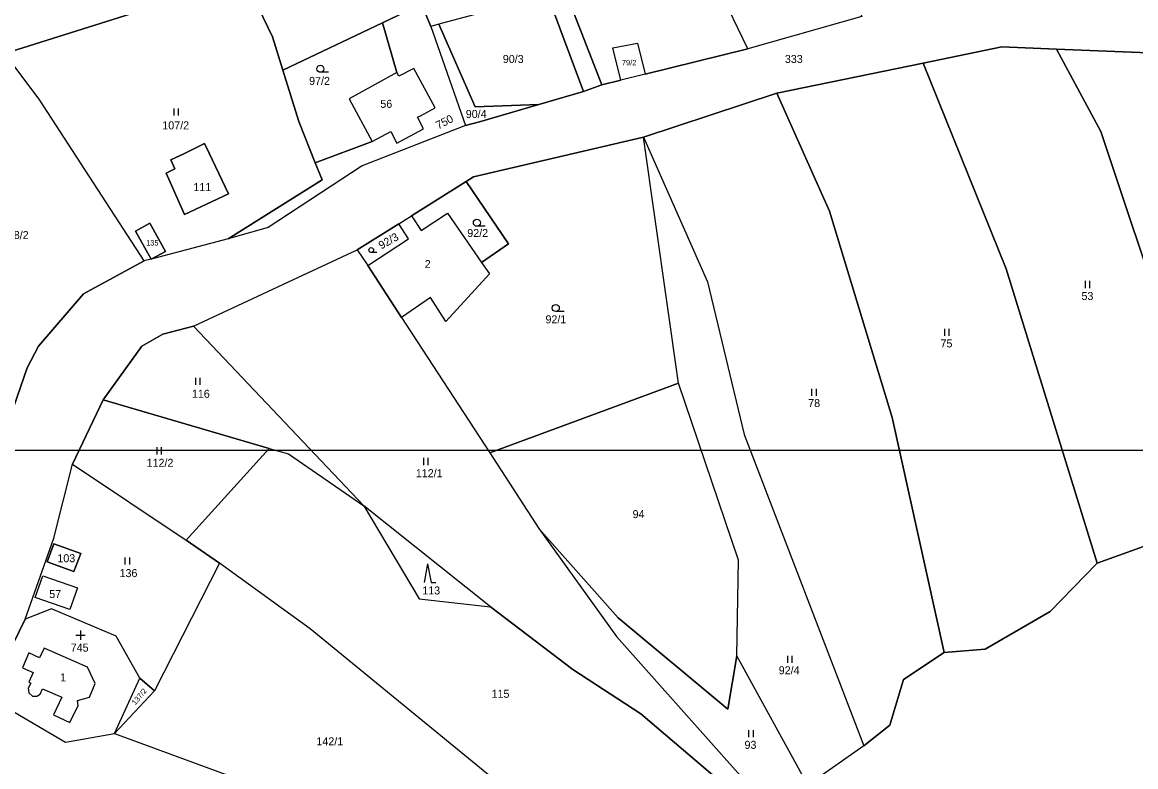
# Model space of a CAD drawing. Extents: x -590606 to -587796, y -1065936 to -1062515.
# Drawn here: x -588986.8 to -588750.2, y -1064072.1 to -1063914 of the extents above; entities that cross this region are included whole.
import ezdxf

# ---------------------------------------------------------------- set-up
doc = ezdxf.new("R2010")
doc.units = 0
for name, color, linetype in [('Default', 7, 'Continuous'), ('Parcela nároku', 7, 'Continuous'), ('Vrstva 30', 7, 'Continuous')]:
    doc.layers.add(name, color=color, linetype=linetype)

msp = doc.modelspace()

# ---------------------------------------------------------------- linework, layer by layer
at = {"layer": 'Default'}
msp.add_lwpolyline([(-590606.42, -1064004.87), (-587796.29, -1064004.87), (-587796.29, -1065935.82), (-590606.42, -1065935.82)], close=True, dxfattribs=at)
at = {"layer": 'Parcela nároku'}
for points in [[(-588933.91, -1063838.81), (-588924.82, -1063834.02), (-588903.58, -1063826.39), (-588900.04, -1063836.93), (-588899.24, -1063839.3), (-588896.62, -1063847.13), (-588895.87, -1063849.37), (-588892.19, -1063861.45), (-588875.17, -1063908.15), (-588898.29, -1063914.41), (-588900.01, -1063914.87), (-588901.55, -1063911.13), (-588901.96, -1063910.16), (-588903.1, -1063907.49), (-588906.06, -1063900.55), (-588920, -1063868.06), (-588927.08, -1063852.06)], [(-588927.08, -1063852.06), (-588920, -1063868.06), (-588906.06, -1063900.55), (-588903.1, -1063907.49), (-588901.96, -1063910.16), (-588910.23, -1063914.1), (-588931.41, -1063924.18), (-588933.62, -1063917.1), (-588939.65, -1063904.58), (-588952.08, -1063879.66), (-588958.1, -1063870.25)], [(-588888.44, -1063860.6), (-588892.19, -1063861.45), (-588875.17, -1063908.15), (-588867.52, -1063928.72), (-588863.64, -1063927.3), (-588875.2, -1063897.61)], [(-589010.57, -1063894.09), (-588981.38, -1063887.88), (-588977.05, -1063880.26), (-588973.04, -1063895.63), (-588966.91, -1063891.55), (-588956.54, -1063883.07), (-588952.08, -1063879.66), (-588939.65, -1063904.58), (-588990.51, -1063920.59)], [(-588999.26, -1063953.09), (-589016.29, -1063972.28), (-588989.28, -1063997.65), (-588985.76, -1063987.39), (-588983.36, -1063982.76), (-588973.8, -1063971.68), (-588960.88, -1063964.65), (-588983.18, -1063930.34), (-588990.51, -1063920.59), (-589010.57, -1063894.09), (-589025.93, -1063892.96), (-589037.53, -1063890.69)], [(-588857.5, -1063900.46), (-588875.2, -1063897.61), (-588863.64, -1063927.3), (-588859.62, -1063926.3), (-588861.33, -1063919.41), (-588856.05, -1063918.43), (-588854.45, -1063925.02), (-588832.67, -1063919.62), (-588836.75, -1063911.14), (-588842.82, -1063898.51)], [(-588836.75, -1063911.14), (-588812.67, -1063901.49), (-588808.45, -1063912.75), (-588832.67, -1063919.62)], [(-588959.37, -1063964.26), (-588960.88, -1063964.65), (-588983.18, -1063930.34), (-588990.51, -1063920.59), (-588939.65, -1063904.58), (-588933.62, -1063917.1), (-588931.41, -1063924.18), (-588928, -1063935.09), (-588924.53, -1063943.8), (-588923.06, -1063947.48), (-588943.02, -1063959.97)], [(-588867.52, -1063928.72), (-588875.17, -1063908.15), (-588898.29, -1063914.41), (-588890.55, -1063931.96), (-588877.01, -1063931.48)], [(-588900.01, -1063914.87), (-588892.64, -1063935.89), (-588914.54, -1063944.45), (-588934.55, -1063957.54), (-588943.02, -1063959.97), (-588923.06, -1063947.48), (-588924.53, -1063943.8), (-588912.46, -1063939.33), (-588908.48, -1063937.2), (-588907.21, -1063939.64), (-588901.57, -1063936.62), (-588902.78, -1063934.15), (-588902.19, -1063933.84), (-588899.04, -1063932.15), (-588903.62, -1063923.81), (-588906.77, -1063925.45), (-588907.2, -1063924.66), (-588910.23, -1063914.1), (-588901.96, -1063910.16), (-588901.55, -1063911.13)], [(-588931.41, -1063924.18), (-588910.23, -1063914.1), (-588907.2, -1063924.66), (-588917.33, -1063930.24), (-588912.46, -1063939.33), (-588924.53, -1063943.8), (-588928, -1063935.09)], [(-588877.01, -1063931.48), (-588890.55, -1063931.96), (-588898.29, -1063914.41), (-588900.01, -1063914.87), (-588892.64, -1063935.89), (-588889.63, -1063935.15)], [(-588861.33, -1063919.41), (-588856.05, -1063918.43), (-588854.45, -1063925.02), (-588859.62, -1063926.3)], [(-588778.71, -1063919.21), (-588795.39, -1063922.64), (-588777.77, -1063966.36), (-588758.46, -1064028.81), (-588732.46, -1064019.48), (-588743.21, -1063980.4), (-588757.62, -1063937.19), (-588767.1, -1063919.67)], [(-588735.23, -1063920.95), (-588767.1, -1063919.67), (-588757.62, -1063937.19), (-588743.21, -1063980.4), (-588732.46, -1064019.48), (-588715.45, -1064013.37), (-588708.45, -1064007.6), (-588711.53, -1063999.16), (-588718.33, -1063967.74)], [(-588795.39, -1063922.64), (-588826.47, -1063929.04), (-588815.32, -1063954.07), (-588801.96, -1063997.88), (-588790.91, -1064047.79), (-588782.24, -1064047.09), (-588768.42, -1064039.12), (-588758.46, -1064028.81), (-588777.77, -1063966.36)], [(-588901.57, -1063936.62), (-588902.78, -1063934.15), (-588902.19, -1063933.84), (-588899.04, -1063932.15), (-588903.62, -1063923.81), (-588906.77, -1063925.45), (-588907.2, -1063924.66), (-588917.33, -1063930.24), (-588912.46, -1063939.33), (-588908.48, -1063937.2), (-588907.21, -1063939.64)], [(-588826.47, -1063929.04), (-588854.83, -1063938.42), (-588841.24, -1063969.13), (-588833.4, -1064001.53), (-588808.01, -1064067.59), (-588802.5, -1064063.26), (-588799.57, -1064053.53), (-588790.91, -1064047.79), (-588801.96, -1063997.88), (-588815.32, -1063954.07)], [(-588948.03, -1063939.74), (-588952.33, -1063941.82), (-588955.24, -1063943.23), (-588954.36, -1063945.14), (-588956.24, -1063946.02), (-588952.34, -1063954.84), (-588942.99, -1063950.39), (-588947.08, -1063941.75)], [(-588952.34, -1063954.84), (-588956.24, -1063946.02), (-588954.36, -1063945.14), (-588955.24, -1063943.23), (-588952.33, -1063941.82), (-588948.03, -1063939.74), (-588947.08, -1063941.75), (-588942.99, -1063950.39)], [(-588887.53, -1063967.43), (-588896.8, -1063977.51), (-588900.07, -1063972.43), (-588906.19, -1063976.64), (-588887.43, -1064005.38), (-588847.35, -1063990.65), (-588854.83, -1063938.42), (-588890.89, -1063946.84), (-588892.47, -1063947.83), (-588883.47, -1063961.02), (-588889.23, -1063964.98)], [(-588841.24, -1063969.13), (-588833.4, -1064001.53), (-588808.01, -1064067.59), (-588819.88, -1064075.96), (-588834.95, -1064048.5), (-588834.59, -1064028.22), (-588847.35, -1063990.65), (-588854.83, -1063938.42)], [(-588892.47, -1063947.83), (-588904.08, -1063955.1), (-588902.04, -1063958.2), (-588896.47, -1063954.55), (-588889.23, -1063964.98), (-588883.47, -1063961.02)], [(-588962.71, -1063958.34), (-588959.66, -1063956.64), (-588956.35, -1063962.63), (-588959.37, -1063964.26)], [(-588959.37, -1063964.26), (-588956.35, -1063962.63), (-588959.66, -1063956.64), (-588962.71, -1063958.34)], [(-588896.47, -1063954.55), (-588889.23, -1063964.98), (-588887.53, -1063967.43), (-588896.8, -1063977.51), (-588900.07, -1063972.43), (-588906.19, -1063976.64), (-588913.38, -1063965.63), (-588904.73, -1063959.96), (-588906.76, -1063956.78), (-588904.08, -1063955.1), (-588902.04, -1063958.2)], [(-588906.76, -1063956.78), (-588915.64, -1063962.34), (-588913.38, -1063965.63), (-588904.73, -1063959.96)], [(-588915.64, -1063962.34), (-588913.38, -1063965.63), (-588906.19, -1063976.64), (-588887.43, -1064005.38), (-588877.06, -1064021.48), (-588860.53, -1064044.44), (-588826.73, -1064082.34), (-588828.85, -1064085.74), (-588837.71, -1064075.83), (-588855.35, -1064060.81), (-588869.78, -1064051.42), (-588887.3, -1064038.11), (-588914.22, -1064016.64), (-588950.41, -1063978.5)], [(-588914.22, -1064016.64), (-588950.41, -1063978.5), (-588956.89, -1063980.22), (-588961.41, -1063982.75), (-588969.56, -1063994.19), (-588934.35, -1064004.48), (-588930.19, -1064005.65)], [(-588834.59, -1064028.22), (-588847.35, -1063990.65), (-588887.43, -1064005.38), (-588877.06, -1064021.48), (-588860.18, -1064040.47), (-588836.86, -1064059.81), (-588834.95, -1064048.5)], [(-588934.35, -1064004.48), (-588969.56, -1063994.19), (-588976.12, -1064007.79), (-588951.97, -1064023.98)], [(-588930.19, -1064005.65), (-588914.22, -1064016.64), (-588902.43, -1064036.41), (-588887.3, -1064038.11), (-588869.78, -1064051.42), (-588855.35, -1064060.81), (-588837.71, -1064075.83), (-588848.79, -1064097.7), (-588855.8, -1064093.72), (-588884.54, -1064076.38), (-588925.65, -1064042.75), (-588944.91, -1064028.83), (-588951.97, -1064023.98), (-588934.35, -1064004.48)], [(-588986.17, -1064040.73), (-588980.05, -1064023.5), (-588976.12, -1064007.79), (-588951.97, -1064023.98), (-588944.91, -1064028.83), (-588958.68, -1064055.94), (-588961.8, -1064053.25), (-588966.81, -1064044.36), (-588980.54, -1064038.51)], [(-588887.3, -1064038.11), (-588914.22, -1064016.64), (-588902.43, -1064036.41)], [(-588819.88, -1064075.96), (-588834.95, -1064048.5), (-588836.86, -1064059.81), (-588860.18, -1064040.47), (-588877.06, -1064021.48), (-588860.53, -1064044.44), (-588826.73, -1064082.34)], [(-588980.04, -1064024.7), (-588974.33, -1064026.8), (-588975.81, -1064030.62), (-588981.51, -1064028.54)], [(-588981.51, -1064028.54), (-588975.81, -1064030.62), (-588974.33, -1064026.8), (-588980.04, -1064024.7)], [(-588925.65, -1064042.75), (-588944.91, -1064028.83), (-588958.68, -1064055.94), (-588967.16, -1064065.03), (-588872.56, -1064099.74), (-588862.95, -1064105.91), (-588855.8, -1064093.72), (-588884.54, -1064076.38)], [(-588984, -1064036.16), (-588982.4, -1064031.52), (-588975.07, -1064034.09), (-588976.69, -1064038.69)], [(-588975.07, -1064034.09), (-588976.69, -1064038.69), (-588984, -1064036.16), (-588982.4, -1064031.52)], [(-588989.95, -1064048.58), (-588993.27, -1064054.69), (-588988.57, -1064060.38), (-588977.56, -1064066.84), (-588967.16, -1064065.03), (-588961.8, -1064053.25), (-588966.81, -1064044.36), (-588980.54, -1064038.51), (-588986.17, -1064040.73)], [(-588974.93, -1064059.06), (-588975.01, -1064057.97), (-588972.5, -1064057.26), (-588971.29, -1064054.42), (-588972.95, -1064050.93), (-588982.15, -1064046.86), (-588983.11, -1064048.93), (-588985.38, -1064047.87), (-588986.76, -1064051.03), (-588984.49, -1064052.04), (-588985.4, -1064054.08), (-588984.98, -1064054.29), (-588985.51, -1064055.41), (-588985.39, -1064056.4), (-588984.58, -1064057.1), (-588983.67, -1064057.07), (-588982.99, -1064056.63), (-588982.49, -1064055.49), (-588978.36, -1064057.28), (-588980.13, -1064061.05), (-588976.69, -1064062.65)], [(-588975.01, -1064057.97), (-588972.5, -1064057.26), (-588971.29, -1064054.42), (-588972.95, -1064050.93), (-588982.15, -1064046.86), (-588983.11, -1064048.93), (-588985.38, -1064047.87), (-588986.76, -1064051.03), (-588984.49, -1064052.04), (-588985.4, -1064054.08), (-588984.98, -1064054.29), (-588985.51, -1064055.41), (-588985.39, -1064056.4), (-588984.58, -1064057.1), (-588983.67, -1064057.07), (-588982.99, -1064056.63), (-588982.49, -1064055.49), (-588978.36, -1064057.28), (-588980.13, -1064061.05), (-588976.69, -1064062.65), (-588974.93, -1064059.06)], [(-588967.16, -1064065.03), (-588961.8, -1064053.25), (-588958.68, -1064055.94)], [(-589004.27, -1064075.98), (-588993.27, -1064054.69), (-588988.57, -1064060.38), (-588977.56, -1064066.84), (-588967.16, -1064065.03), (-588872.56, -1064099.74), (-588862.95, -1064105.91), (-588858.6, -1064108.28), (-588879.39, -1064154.14), (-588886.85, -1064148.4), (-588915.21, -1064132.5), (-588968.76, -1064107.97), (-589010.47, -1064096.24)]]:
    msp.add_lwpolyline(points, close=True, dxfattribs=at)
for points in [[(-588808.45, -1063912.75), (-588832.67, -1063919.62), (-588854.45, -1063925.02), (-588859.62, -1063926.3), (-588863.64, -1063927.3), (-588867.52, -1063928.72), (-588877.01, -1063931.48), (-588889.63, -1063935.15), (-588892.64, -1063935.89), (-588914.54, -1063944.45), (-588934.55, -1063957.54), (-588943.02, -1063959.97), (-588959.37, -1063964.26), (-588960.88, -1063964.65), (-588973.8, -1063971.68), (-588983.36, -1063982.76), (-588985.76, -1063987.39), (-588989.28, -1063997.65)], [(-588989.95, -1064048.58), (-588986.17, -1064040.73), (-588980.05, -1064023.5), (-588976.12, -1064007.79), (-588969.56, -1063994.19), (-588961.41, -1063982.75), (-588956.89, -1063980.22), (-588950.41, -1063978.5), (-588915.64, -1063962.34), (-588906.76, -1063956.78), (-588904.08, -1063955.1), (-588892.47, -1063947.83), (-588890.89, -1063946.84), (-588854.83, -1063938.42), (-588826.47, -1063929.04), (-588795.39, -1063922.64), (-588778.71, -1063919.21), (-588767.1, -1063919.67), (-588735.23, -1063920.95)], [(-588732.46, -1064019.48), (-588758.46, -1064028.81), (-588768.42, -1064039.12), (-588782.24, -1064047.09), (-588790.91, -1064047.79), (-588799.57, -1064053.53), (-588802.5, -1064063.26), (-588808.01, -1064067.59), (-588819.88, -1064075.96), (-588826.73, -1064082.34), (-588828.85, -1064085.74), (-588838.02, -1064101.01), (-588845.92, -1064113.72), (-588853.47, -1064131.31), (-588871.45, -1064160.3), (-588878.22, -1064170.94), (-588883.55, -1064181.89), (-588899.01, -1064200.35), (-588931.73, -1064246.65), (-588943.19, -1064264.43), (-588952.56, -1064282.48)]]:
    msp.add_lwpolyline(points, dxfattribs=at)
at = {"layer": 'Vrstva 30'}
for p, q in [((-588921.69, -1063924.61), (-588923.44, -1063924.61)), ((-588954.6, -1063932.31), (-588954.6, -1063933.81)), ((-588953.58, -1063933.81), (-588953.58, -1063932.31)), ((-588888.45, -1063957.31), (-588890.2, -1063957.31)), ((-588911.47, -1063962.85), (-588912.64, -1063962.85)), ((-588761.01, -1063968.92), (-588761.01, -1063970.42)), ((-588759.98, -1063970.42), (-588759.98, -1063968.92)), ((-588871.69, -1063975.41), (-588873.44, -1063975.41)), ((-588790.89, -1063979.09), (-588790.89, -1063980.59)), ((-588789.86, -1063980.59), (-588789.86, -1063979.09)), ((-588950, -1063989.49), (-588950, -1063990.99)), ((-588948.97, -1063990.99), (-588948.97, -1063989.49)), ((-588819.11, -1063991.8), (-588819.11, -1063993.3)), ((-588818.08, -1063993.3), (-588818.08, -1063991.8)), ((-588958.2, -1064004.23), (-588958.2, -1064005.73)), ((-588957.18, -1064005.73), (-588957.18, -1064004.23)), ((-588901.57, -1064006.5), (-588901.57, -1064008)), ((-588900.55, -1064008), (-588900.55, -1064006.5)), ((-588964.98, -1064027.6), (-588964.98, -1064029.1)), ((-588963.95, -1064029.1), (-588963.95, -1064027.6)), ((-588900.67, -1064028.96), (-588901.41, -1064032.96)), ((-588900.67, -1064028.96), (-588899.94, -1064032.96)), ((-588899.94, -1064032.96), (-588898.94, -1064032.96)), ((-588975.41, -1064044.13), (-588973.41, -1064044.13)), ((-588974.41, -1064043.13), (-588974.41, -1064045.13)), ((-588824.24, -1064048.48), (-588824.24, -1064049.98)), ((-588823.21, -1064049.98), (-588823.21, -1064048.48)), ((-588832.47, -1064064.28), (-588832.47, -1064065.78)), ((-588831.45, -1064065.78), (-588831.45, -1064064.28))]:
    msp.add_line(p, q, dxfattribs=at)
for centre, radius in [((-588923.44, -1063923.86), 0.75), ((-588890.2, -1063956.56), 0.75), ((-588912.64, -1063962.35), 0.503), ((-588873.44, -1063974.66), 0.75)]:
    msp.add_circle(centre, radius, dxfattribs=at)

# ---------------------------------------------------------------- texts
at = {"layer": 'Parcela nároku'}
for s, height, p in [('90/3', 1.7, (-588884.69, -1063922.63)), ('333', 1.7, (-588824.77, -1063922.63)), ('79/2', 1.14, (-588859.38, -1063923.13)), ('97/2', 1.7, (-588925.84, -1063927.29)), ('56', 1.7, (-588910.71, -1063932.16)), ('90/4', 1.7, (-588892.56, -1063934.31)), ('107/2', 1.7, (-588957.02, -1063936.73)), ('111', 1.7, (-588950.43, -1063949.83)), ('118/2', 1.7, (-588991.11, -1063960.02)), ('92/2', 1.7, (-588892.24, -1063959.59)), ('135', 1.14, (-588960.46, -1063961.39)), ('2', 1.7, (-588901.29, -1063966.19)), ('53', 1.7, (-588761.76, -1063972.96)), ('92/1', 1.7, (-588875.63, -1063977.92)), ('75', 1.7, (-588791.71, -1063983.03)), ('116', 1.7, (-588950.74, -1063993.72)), ('78', 1.7, (-588819.82, -1063995.69)), ('112/2', 1.7, (-588960.36, -1064008.38)), ('112/1', 1.7, (-588903.17, -1064010.58)), ('94', 1.7, (-588857.12, -1064019.27)), ('103', 1.7, (-588979.32, -1064028.64)), ('136', 1.7, (-588966.11, -1064031.8)), ('57', 1.7, (-588981.05, -1064036.24)), ('113', 1.7, (-588901.8, -1064035.48)), ('745', 1.7, (-588976.48, -1064047.61)), ('92/4', 1.7, (-588826.08, -1064052.43)), ('1', 1.7, (-588978.73, -1064053.95)), ('115', 1.7, (-588887.08, -1064057.42)), ('142/1', 1.7, (-588924.29, -1064067.52)), ('93', 1.7, (-588833.34, -1064068.26))]:
    msp.add_text(s, height=height, dxfattribs=at).set_placement(p)
for s, height, rotation, p in [('750', 1.7, 27.2666, (-588898.39, -1063936.76)), ('92/3', 1.7, 29.4571, (-588910.5, -1063962.25)), ('137/2', 1.14, 50.18, (-588962.75, -1064059.06))]:
    msp.add_text(s, height=height, rotation=rotation, dxfattribs=at).set_placement(p)

doc.saveas('drawing.dxf')
